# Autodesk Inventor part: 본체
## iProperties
Created: 2015-05
Part Number: 본체
Document SubType Name: Modeling
Designer: Administrator
Density: 1.06 g/cm^3
Material: ABS 플라스틱
Mass: 32.0237 g
Surface Area: 312.839 cm^2
Volume: 30.211 cm^3
Author: Administrator
